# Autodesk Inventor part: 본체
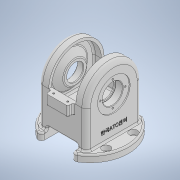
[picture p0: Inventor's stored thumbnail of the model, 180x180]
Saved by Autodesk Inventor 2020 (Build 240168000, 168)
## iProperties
Created: 2024-08
Part Number: 본체
Material: 일반
Document SubType Name: Modeling
Designer: oem
Density: 1 g/cm^3
Appearance: 기본값
Mass: 444.002 g
Surface Area: 1052.82 cm^2
Volume: 444.002 cm^3
Author: oem
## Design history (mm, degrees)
sketch "스케치2"
  geometry: L1 (0, 51)-(-81, 51); L2 (-81, 51)-(-81, -51); L3 (-81, -51)-(0, -51); L4 (51, 0)-(51, 0); A1 r 51 centre (0, 0) between (51, 0) and (0, 51); A2 r 51 centre (0, 0) between (0, -51) and (51, 0); 3 further points
  constraints: 8 end point, 4 point on circle, 4 tangent, 2 centre point, 2 parallel, 2 point on line, 1 concentric, 1 horizontal, 1 perpendicular
  dimensions: "d3" = 132 distance of L2.end point (51, -51); "d4" = 102 distance of L1.end L2.end; "d5" = 51 radius of A1; "d6" = 51 distance from line of point (0, 0) L1; "d7" = 81 distance from line of point (0, 0) L2
extrude "돌출2" new body sketch "스케치2" distance "d8" = 88; taper "d9" = 0 deg
sketch "스케치3"
  geometry: L1 (-69, 132)-(-19, 132); L2 (-19, 132)-(-19, 81); L3 (-19, 81)-(-69, 81); L4 (-69, 81)-(-69, 132); L5 (0, 81)-(0, 81) reference; L6 (0, 81)-(-88, 81) reference; L7 (-88, 81)-(-88, 81) reference; L8 (0, 81)-(-88, 81) reference; L9 (0, 132)-(-88, 132) reference; L10 (-88, 0)-(-88, 81) reference; 1 further point
  constraints: 8 end point, 2 parallel, 1 horizontal, 1 perpendicular
  dimensions: "d10" = 50 distance of L1.start L1.end; "d11" = 0 distance between parallel lines of L9 L1; "d12" = 19 distance between parallel lines of L4 L10; "d13" = 51 distance of L1.end L2.end
extrude "돌출3" cut sketch "스케치3" extent not by distance; stored distance "d14" = 0; taper "d15" = 0 deg
sketch "스케치6"
  geometry: L1 (0, 102)-(0, 0) reference; L2 (0, 0)-(-88, 0) reference; C1 r 71 at (-44, 51); 2 further points
  constraints: 1 centre point, 1 coincident
  dimensions: "d17" = 44 distance from line of point (-44, 51) L1; "d18" = 51 distance from line of point (-44, 51) L2; "d19" = 142 diameter of C1
extrude "돌출4" join sketch "스케치6" distance "d20" = 13; taper "d21" = 0 deg
node "작업 평면1"
sketch "스케치7"
  geometry: L1 (53, -81)-(-3, -81); L2 (-3, -81)-(-3, -62); L3 (-3, -62)-(53, -62); L4 (53, -62)-(53, -81); L5 (-46, -81)-(96, -81) reference; 1 further point
  constraints: 8 end point, 2 parallel, 1 horizontal, 1 horizontal alignment, 1 perpendicular
  dimensions: "d23" = 56 distance of L1.start L1.end; "d24" = 19 distance of L3.end L1.start; "d25" = 43 distance from line of L4 L5.end
extrude "돌출5" cut sketch "스케치7" extent not by distance; stored distance "d26" = 0; taper "d27" = 0 deg
sketch "스케치9"
  geometry: A1 r 51 centre (0, 0) between (51, 0) and (-51, 0) reference; 2 further points
  constraints: 1 coincident
sketch "스케치10"
  geometry: A1 r 51 centre (0, 0) between (51, 0) and (-51, 0) reference; 2 further points
  constraints: 1 coincident
sketch "스케치11"
  geometry: L1 (5, 0)-(45, 0); L2 (45, 0)-(45, -20); L3 (45, -20)-(5, -20); L4 (5, -20)-(5, 0); L5 (-19, -68)-(-19, 0) reference; 1 further point
  constraints: 8 end point, 2 parallel, 1 horizontal, 1 horizontal alignment, 1 perpendicular
  dimensions: "d42" = 40 distance of L2.end L3.end; "d43" = 20 distance of L1.end L2.end; "d44" = 24 distance between parallel lines of L4 L5
extrude "돌출6" join sketch "스케치11" distance "d45" = 10; taper "d46" = 0 deg
sketch "스케치12"
  geometry: L1 (12, -3)-(38, -3); L2 (38, -3)-(38, 105); L3 (38, 105)-(12, 105); L4 (12, 105)-(12, -3); L5 (5, 102)-(5, 112) reference; 1 further point
  constraints: 8 end point, 2 parallel, 1 horizontal, 1 perpendicular
  dimensions: "d47" = 26 distance of L2.end L3.end; "d48" = 108 distance of L1.end L2.end; "d49" = 54 distance from line of L3 point (69, 51); "d50" = 7 distance from line of L3.end L5
hole "구멍3" sketch "스케치12" at (38, -3), (12, -3), (12, 105), (38, 105) diameter "d51" = 3.242; stored, may be unused: countersink angle "d55" = 90 deg, drill point angle "d57" = 118 deg; dims "d52" = 8, "d53" = 60, "d54" = 2, "d56" = 10
sketch "스케치13"
  geometry: L1 (51, 0)-(51, -68) reference; L2 (-51, -68)-(-51, 0) reference; L3 (-46, -41)-(-46, 0); L4 (46, 0)-(46, -41); L5 (-46, -41)-(46, -41); L6 (65.246, -81)-(-65.246, -81) reference; A1 r 51 centre (0, 0) between (51, 0) and (-51, 0) reference; A2 r 46 centre (0, 0) between (46, 0) and (-46, 0); 1 further point
  constraints: 6 end point, 2 point on circle, 1 centre point, 1 horizontal
  dimensions: "d58" = 5 radial gap between concentric circles of A1 A2; "d59" = 40 distance between parallel lines of L5 L6
extrude "돌출7" cut sketch "스케치13" distance "d60" = 14; taper "d61" = 0 deg
sketch "스케치14"
  geometry: L1 (51, 0)-(51, -68) reference; L2 (-51, -68)-(-51, 0) reference; L3 (-46, -41)-(-46, 0); L4 (46, 0)-(46, -41); L5 (-46, -41)-(46, -41); L6 (65.246, -81)-(-65.246, -81) reference; A1 r 46 centre (0, 0) between (46, 0) and (-46, 0) reference; A2 r 51 centre (0, 0) between (51, 0) and (-51, 0) reference; A3 r 46 centre (0, 0) between (46, 0) and (-46, 0); 1 further point
  constraints: 6 end point, 2 point on circle, 1 centre point, 1 horizontal
  dimensions: "d62" = 5 radial gap between concentric circles of A2 A3; "d63" = 40 distance between parallel lines of L5 L6
extrude "돌출8" cut sketch "스케치14" distance "d64" = 14; taper "d65" = 0 deg
sketch "스케치15"
  geometry: L1 (46, -41)-(46, 0) reference; L2 (-46, 0)-(-46, -41) reference; L3 (-46, -41)-(46, -41) reference; L4 (-46, -41)-(46, -41); L5 (46, -41)-(46, 0); L6 (46, 0)-(-46, 0); L7 (-46, 0)-(-46, -41); 1 further point
  constraints: 8 end point, 2 parallel, 1 horizontal, 1 perpendicular
extrude "돌출9" cut sketch "스케치15" stored distance "d66" = 14; taper "d67" = 0 deg
sketch "스케치16"
  geometry: C1 r 33.5 at (0, 0); 1 further point
  constraints: 1 centre point, 1 coincident
  dimensions: "d68" = 67 diameter of C1
extrude "돌출10" join sketch "스케치16" distance "d69" = 12; taper "d70" = -45 deg
node "작업 평면2"
sketch "스케치17"
  geometry: A1 r 51 centre (0, 0) between (51, 0) and (-51, 0) reference; 2 further points
  constraints: 1 coincident
hole "구멍4" sketch "스케치17" at (0, 0) diameter "d72" = 37; stored, may be unused: countersink angle "d76" = 90 deg, drill point angle "d78" = 0 deg; dims "d73" = 8, "d74" = 60, "d75" = 2, "d77" = 15
sketch "스케치18"
  geometry: A1 r 51 centre (0, 0) between (51, 0) and (-51, 0) reference; 2 further points
  constraints: 1 coincident
hole "구멍5" sketch "스케치18" at (0, 0) diameter "d79" = 37; stored, may be unused: countersink angle "d83" = 90 deg, drill point angle "d85" = 0 deg; dims "d80" = 8, "d81" = 60, "d82" = 2, "d84" = 15
sketch "스케치19"
  geometry: C1 r 18.5 at (0, 0) reference; 2 further points
  constraints: 1 coincident
hole "구멍6" sketch "스케치19" at (0, 0) diameter "d86" = 32; stored, may be unused: countersink angle "d90" = 90 deg, drill point angle "d92" = 0 deg; dims "d87" = 8, "d88" = 60, "d89" = 2, "d91" = 15
sketch "스케치20"
  geometry: L1 (-65.246, -81)-(65.246, -81) reference; 2 further points
  constraints: 1 vertical alignment, 1 other
  dimensions: "d93" = 30 distance from line of point (0, -51) L1
feature "엠보싱1" sketch "스케치20" dims "d94" = 0.5, "d95" = 0
sketch "스케치21"
  geometry: L1 (-99, -26)-(11, -26); L2 (11, -26)-(11, -76); L3 (11, -76)-(-99, -76); L4 (-99, -76)-(-99, -26); A1 r 71 centre (-44, -51) between (-16, -116.246) and (-16, 14.246) reference; 1 further point
  constraints: 8 end point, 2 parallel, 1 horizontal, 1 perpendicular
  dimensions: "d96" = 50 distance of L1.end L2.end; "d97" = 110 distance of L1.start L1.end; "d98" = 25 distance from line of A1.centre L1; "d99" = 55 distance from line of A1.centre L2
hole "구멍7" sketch "스케치21" at (11, -76), (11, -26), (-99, -76), (-99, -26) diameter "d100" = 9; stored, may be unused: countersink angle "d104" = 90 deg, drill point angle "d106" = 0 deg; dims "d101" = 8, "d102" = 15, "d103" = 8.8, "d105" = 15
sketch "스케치22"
  geometry: L1 (0, 0)-(23, 0)
  constraints: 2 end point, 1 horizontal
  dimensions: "d107" = 23 distance of L1.start L1.end
hole "구멍8" sketch "스케치22" at (23, 0) diameter "d108" = 3.242; stored, may be unused: countersink angle "d112" = 90 deg, drill point angle "d114" = 118 deg; dims "d109" = 8, "d110" = 15, "d111" = 8.8, "d113" = 10
node "작업 평면3"
sketch "스케치23"
  geometry: L1 (72, -102)-(72, 0) reference; L2 (48, 0)-(8, 0) reference; C1 r 30 at (28, -51); 1 further point
  constraints: 1 centre point
  dimensions: "d119" = 60 diameter of C1; "d120" = 44 distance from line of C1.centre L1; "d121" = 51 distance from line of C1.centre L2
extrude "돌출11" cut sketch "스케치23" extent not by distance; stored distance "d122" = 22; taper "d123" = 0 deg
sketch "스케치24"
  geometry: L1 (0, 0)-(23, 0); A1 r 30 centre (0, 0) between (28, 10.77) and (-28, 10.77) reference; 1 further point
  constraints: 2 end point, 1 horizontal
  dimensions: "d124" = 23 distance of L1.start L1.end
hole "구멍9" sketch "스케치24" at (23, 0) diameter "d125" = 3.242; stored, may be unused: countersink angle "d129" = 90 deg, drill point angle "d131" = 118 deg; dims "d126" = 8, "d127" = 15, "d128" = 8.8, "d130" = 10
sketch "스케치25"
  geometry: C1 r 30 at (0, 0) reference; 2 further points
  constraints: 1 coincident
hole "구멍10" sketch "스케치25" at (0, 0) diameter "d135" = 22; stored, may be unused: countersink angle "d139" = 90 deg, drill point angle "d141" = 0 deg; dims "d136" = 8, "d137" = 28, "d138" = 15, "d140" = 40
fillet "모깎기1" dims "d142" = 8
chamfer "모따기1" distance "d143" = 1; stored, may be unused: second distance "d144" = 2, angle "d145" = 45 deg
fillet "모깎기2" dims "d146" = 0.3
fillet "모깎기3" dims "d147" = 6
fillet "모깎기4" dims "d148" = 3
fillet "모깎기5" dims "d149" = 3
fillet "모깎기6" dims "d150" = 3
fillet "모깎기7" dims "d151" = 3
fillet "모깎기8" dims "d152" = 3
node "솔리드2"
mirror "미러1"
mirror "미러2"
pattern_circular "원형 패턴1" dims angle "d116" = 360 deg
mirror "미러3"
pattern_circular "원형 패턴2" dims angle "d133" = 360 deg
node "투영된 루프1"
feature "A9D066F2-1C7D-4E18-AEED-F7BC21143FA4" dims "d72" = 37, "d73" = 8, "d74" = 60, "d75" = 2, "d76" = 90 deg, "d77" = 15, "d78" = 0
other parameters: "d22" = 78, "d71" = -44, "d118" = -3
